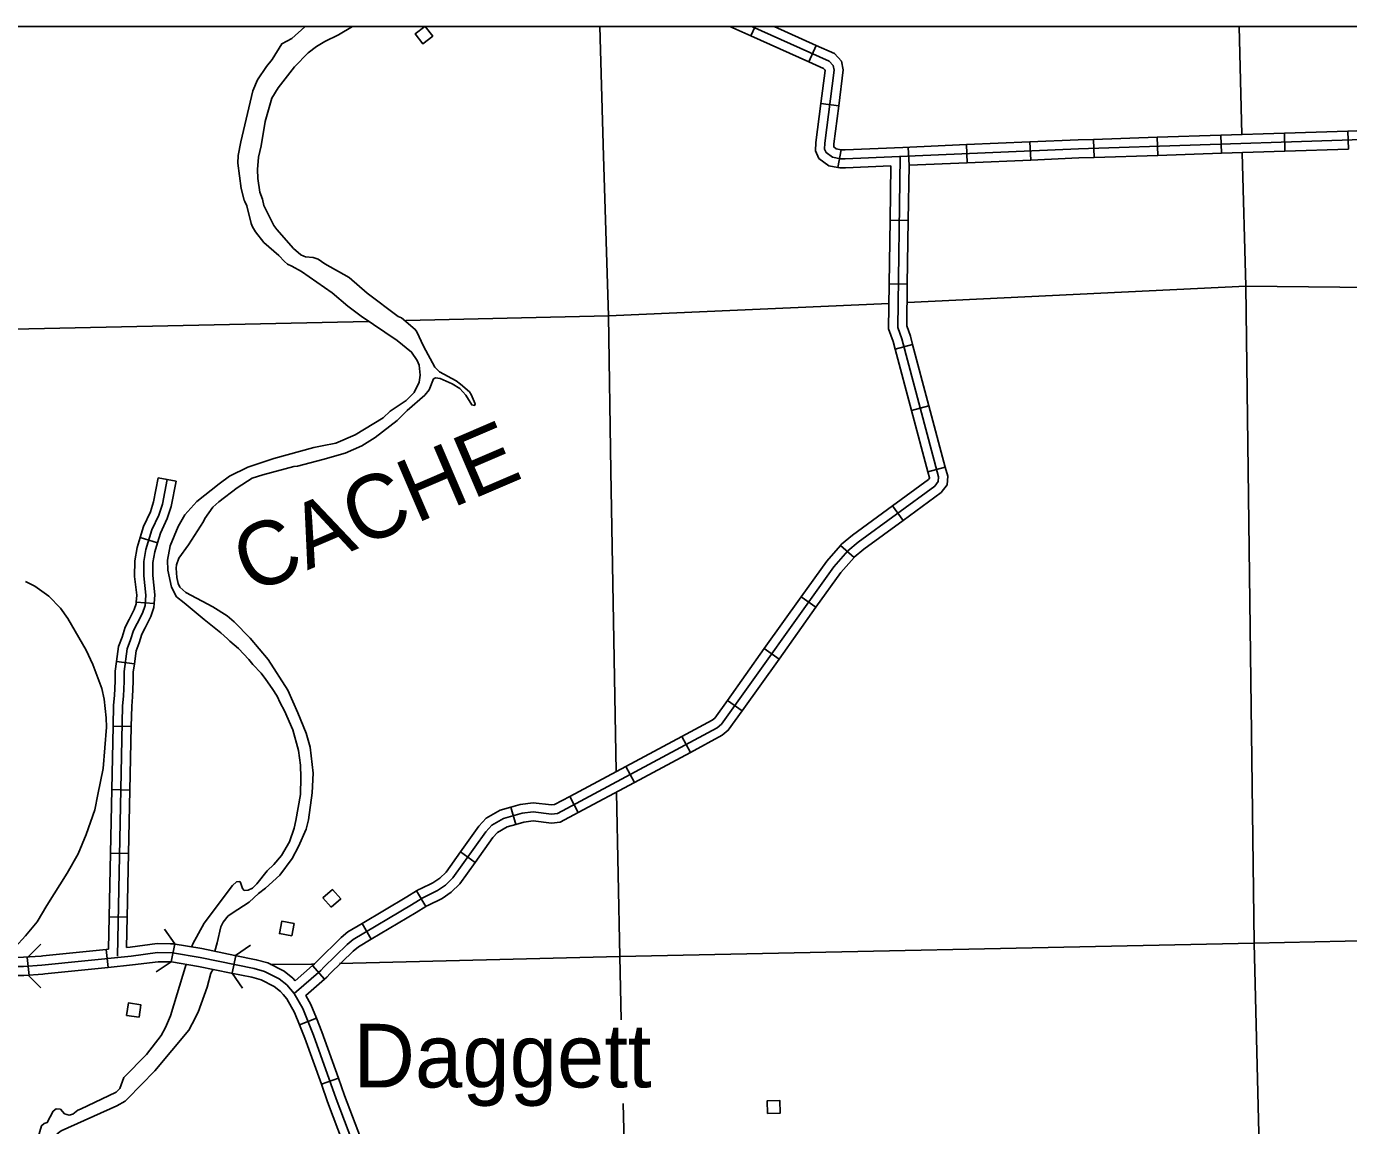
# Model space of a CAD drawing. Extents: x 1084508 to 1142749, y 1057638 to 1093403.
# Drawn here: x 1089174 to 1092618, y 1090540 to 1093403 of the extents above; entities that cross this region are included whole.
import ezdxf

# ---------------------------------------------------------------- set-up
doc = ezdxf.new("R2010")
doc.units = 0
for name, color, linetype in [('DSN_DRFT_Named-Boundary', 7, 'Continuous'), ('Level 24', 7, 'Continuous'), ('Level 32', 7, 'Continuous'), ('Level 35', 7, 'Continuous'), ('Level 38', 7, 'Continuous'), ('Level 5', 7, 'Continuous'), ('Level 56', 7, 'Continuous'), ('Level 9', 7, 'Continuous')]:
    doc.layers.add(name, color=color, linetype=linetype)

msp = doc.modelspace()

# ---------------------------------------------------------------- linework, layer by layer
at = {"layer": 'DSN_DRFT_Named-Boundary'}
msp.add_lwpolyline([(1084507.9, 1057640), (1142749.2, 1057640), (1142749.2, 1093403.4), (1084507.9, 1093403.4)], close=True, dxfattribs=at)
at = {"layer": 'Level 32'}
for p, q in [((1091006.5, 1093403.4), (1091061.2, 1093378.8)), ((1091061.2, 1093378.8), (1091072.2, 1093403.4)), ((1091121.4, 1093403.4), (1091231.6, 1093353.9)), ((1091212.3, 1093310.9), (1091231.6, 1093353.9)), ((1091243.2, 1093202.5), (1091289.9, 1093196.5)), ((1092617.9, 1093083.7), (1092616.3, 1093130.8)), ((1091624.4, 1093048.4), (1091622.4, 1093095.4)), ((1091790, 1093055.4), (1091788, 1093102.4)), ((1091955.3, 1093062), (1091953.8, 1093109.1)), ((1092121, 1093067.4), (1092119.4, 1093114.5)), ((1092286.6, 1093072.9), (1092285.1, 1093119.9)), ((1092452.2, 1093078.3), (1092450.7, 1093125.4)), ((1091287.9, 1093036.1), (1091296.6, 1093082.3)), ((1091473.1, 1093041.5), (1091471.1, 1093088.6)), ((1091423.9, 1092898.3), (1091471, 1092897.6)), ((1091421.6, 1092732.6), (1091468.6, 1092731.9)), ((1091436.8, 1092563), (1091482.3, 1092575.1)), ((1091479.4, 1092402.9), (1091524.9, 1092415)), ((1091522.1, 1092242.7), (1091567.6, 1092254.8)), ((1089517.7, 1092227.7), (1089563.9, 1092218.6)), ((1091430.1, 1092154.5), (1091457.9, 1092116.6)), ((1089470.4, 1092072.2), (1089515.4, 1092058.4)), ((1091294.5, 1092050.9), (1091329.8, 1092019.7)), ((1089460.2, 1091903.4), (1089507.1, 1091899.7)), ((1091192.4, 1091917.5), (1091230.7, 1091890.2)), ((1091096.1, 1091782.6), (1091134.4, 1091755.3)), ((1089408.7, 1091748.7), (1089455.4, 1091742.5)), ((1090999.8, 1091647.7), (1091038.2, 1091620.4)), ((1089400.1, 1091580.8), (1089447.2, 1091579.8)), ((1090881.5, 1091553.6), (1090903.7, 1091512.1)), ((1090735.4, 1091475.4), (1090757.6, 1091433.9)), ((1089396.6, 1091415.1), (1089443.7, 1091414.1)), ((1090589.2, 1091397.2), (1090611.5, 1091355.7)), ((1090435.5, 1091369.6), (1090448.6, 1091324.4)), ((1089393.2, 1091249.4), (1089440.3, 1091248.4)), ((1090304.4, 1091252.8), (1090342.7, 1091225.5)), ((1090190.2, 1091151.3), (1090214.8, 1091111.1)), ((1089389.7, 1091083.7), (1089436.8, 1091082.7)), ((1090048.3, 1091066.3), (1090072.4, 1091025.8)), ((1089386.7, 1090951.8), (1089382, 1090998.7)), ((1089551.5, 1090966.7), (1089560.4, 1091013)), ((1089181.2, 1090931), (1089176.4, 1090977.8)), ((1089709.9, 1090936.8), (1089719.3, 1090982.9)), ((1089919.5, 1090956.8), (1089950.4, 1090921.3)), ((1089885.8, 1090802.3), (1089929.5, 1090819.8)), ((1089942.3, 1090647.5), (1089986.7, 1090663.3))]:
    msp.add_line(p, q, dxfattribs=at)
for points in [[(1091061.2, 1093378.8), (1091212.3, 1093310.9)], [(1091064, 1093403.4), (1091264.8, 1093313.2), (1091275.5, 1093301.4), (1091278, 1093289.3), (1091253.8, 1093099.2), (1091253.1, 1093084), (1091257.2, 1093074.7), (1091273.4, 1093062.8), (1091294.9, 1093058.7)], [(1091231.6, 1093353.9), (1091278.9, 1093332.6), (1091297.3, 1093312.5), (1091301.9, 1093290.2), (1091289.9, 1093196.5)], [(1091212.3, 1093310.9), (1091250.7, 1093293.7), (1091253.8, 1093290.3), (1091254.2, 1093288.4), (1091243.2, 1093202.5)], [(1091243.2, 1093202.5), (1091230.3, 1093101.2), (1091229.4, 1093079.6), (1091238.2, 1093059.5), (1091263.8, 1093040.6), (1091287.9, 1093036.1)], [(1091289.9, 1093196.5), (1091277.3, 1093097.2), (1091276.9, 1093089.5), (1091283.1, 1093084.9), (1091296.6, 1093082.3)], [(1091294.9, 1093058.7), (1091307.1, 1093058.4), (1091914.4, 1093084.2), (1092865.4, 1093115.4), (1093339.9, 1093125.6), (1093745.9, 1093130.1), (1093949.8, 1093129.8)], [(1092450.7, 1093125.4), (1092616.3, 1093130.8)], [(1092616.3, 1093130.8), (1092782, 1093136.2)], [(1091456.8, 1093088.4), (1091622.4, 1093095.4)], [(1091622.4, 1093095.4), (1091788, 1093102.4)], [(1091788, 1093102.4), (1091913.5, 1093107.8), (1091953.8, 1093109.1)], [(1091953.8, 1093109.1), (1092119.4, 1093114.5)], [(1092119.4, 1093114.5), (1092285.1, 1093119.9)], [(1092285.1, 1093119.9), (1092450.7, 1093125.4)], [(1091449.7, 1093063.7), (1091443.5, 1092619.3), (1091454.1, 1092589.5), (1091549.9, 1092229.6), (1091549.1, 1092217.6), (1091540, 1092205.9), (1091340.7, 1092059.9), (1091314, 1092037.4), (1091277.1, 1091995.7), (1090984.5, 1091585.7), (1090973.4, 1091576.1), (1090557.2, 1091353.3)], [(1091296.6, 1093082.3), (1091297.4, 1093082.2), (1091306.8, 1093082), (1091456.8, 1093088.4)], [(1091790, 1093055.4), (1091915.3, 1093060.7), (1091955.3, 1093062)], [(1091955.3, 1093062), (1092121, 1093067.4)], [(1092121, 1093067.4), (1092286.6, 1093072.9)], [(1092286.6, 1093072.9), (1092452.2, 1093078.3)], [(1092452.2, 1093078.3), (1092617.9, 1093083.7)], [(1091287.9, 1093036.1), (1091292.5, 1093035.2), (1091307.3, 1093034.9), (1091425.9, 1093039.9)], [(1091425.9, 1093039.9), (1091423.9, 1092898.3)], [(1091473, 1093041.9), (1091471, 1092897.6)], [(1091473, 1093041.9), (1091624.4, 1093048.4)], [(1091624.4, 1093048.4), (1091790, 1093055.4)], [(1091423.9, 1092898.3), (1091421.6, 1092732.6)], [(1091471, 1092897.6), (1091468.6, 1092731.9)], [(1091421.6, 1092732.6), (1091419.9, 1092615.4), (1091431.6, 1092582.5), (1091436.8, 1092563)], [(1091468.6, 1092731.9), (1091467.1, 1092623.2), (1091476.6, 1092596.4), (1091482.3, 1092575.1)], [(1091436.8, 1092563), (1091479.4, 1092402.9)], [(1091482.3, 1092575.1), (1091524.9, 1092415)], [(1091524.9, 1092415), (1091567.6, 1092254.8)], [(1091479.4, 1092402.9), (1091522.1, 1092242.7)], [(1091522.1, 1092242.7), (1091526.2, 1092227.3), (1091526.1, 1092226.4), (1091523.5, 1092223), (1091430.1, 1092154.5)], [(1091567.6, 1092254.8), (1091573.7, 1092231.9), (1091572.1, 1092208.8), (1091556.6, 1092188.9), (1091457.9, 1092116.6)], [(1089540.8, 1092223.1), (1089528.2, 1092158.7), (1089519.1, 1092130.3), (1089501, 1092091.9), (1089485.3, 1092040.3), (1089479.9, 1092009.1), (1089479.6, 1091972), (1089485.2, 1091921.8), (1089483.1, 1091894.6), (1089476.3, 1091874.9), (1089462.7, 1091847.5), (1089453.1, 1091829.7), (1089445.5, 1091805), (1089436.9, 1091782), (1089429, 1091722.5), (1089429.1, 1091697.2), (1089427, 1091658.8), (1089424.8, 1091633.5), (1089411.1, 1090981.6)], [(1089517.7, 1092227.7), (1089505.4, 1092164.6), (1089497.1, 1092139), (1089479, 1092100.4), (1089470.4, 1092072.2)], [(1089563.9, 1092218.6), (1089551, 1092152.9), (1089541, 1092121.7), (1089523, 1092083.4), (1089515.4, 1092058.4)], [(1091430.1, 1092154.5), (1091326.2, 1092078.4), (1091297.5, 1092054.3), (1091294.5, 1092050.9)], [(1091457.9, 1092116.6), (1091355.2, 1092041.3), (1091330.4, 1092020.5), (1091329.8, 1092019.7)], [(1089470.4, 1092072.2), (1089462.3, 1092045.7), (1089456.3, 1092011.3), (1089456, 1091970.8), (1089461.6, 1091921.4), (1089460.2, 1091903.4)], [(1089515.4, 1092058.4), (1089508.2, 1092034.8), (1089503.4, 1092007), (1089503.2, 1091973.2), (1089508.9, 1091922.2), (1089507.1, 1091899.7)], [(1091294.5, 1092050.9), (1091258.6, 1092010.4), (1091192.4, 1091917.5)], [(1091329.8, 1092019.7), (1091295.5, 1091981), (1091230.7, 1091890.2)], [(1089460.2, 1091903.4), (1089459.9, 1091899.5), (1089454.5, 1091884), (1089441.8, 1091858.3), (1089431.3, 1091838.8), (1089423.2, 1091812.6), (1089413.9, 1091787.8), (1089408.7, 1091748.7)], [(1089507.1, 1091899.7), (1089506.3, 1091889.8), (1089498, 1091865.8), (1089483.6, 1091836.6), (1089474.9, 1091820.5), (1089467.8, 1091797.4), (1089459.9, 1091776.3), (1089455.4, 1091742.5)], [(1091192.4, 1091917.5), (1091096.1, 1091782.6)], [(1091230.7, 1091890.2), (1091134.4, 1091755.3)], [(1091096.1, 1091782.6), (1090999.8, 1091647.7)], [(1091134.4, 1091755.3), (1091038.2, 1091620.4)], [(1089408.7, 1091748.7), (1089405.5, 1091724.1), (1089405.5, 1091697.9), (1089403.5, 1091660.5), (1089401.2, 1091634.8), (1089400.1, 1091580.8)], [(1089455.4, 1091742.5), (1089452.6, 1091721), (1089452.6, 1091696.6), (1089450.5, 1091657.2), (1089448.3, 1091632.3), (1089447.2, 1091579.8)], [(1090999.8, 1091647.7), (1090967, 1091601.7), (1090960, 1091595.7), (1090881.5, 1091553.6)], [(1091038.2, 1091620.4), (1091002, 1091569.8), (1090986.7, 1091556.6), (1090903.7, 1091512.1)], [(1089400.1, 1091580.8), (1089396.6, 1091415.1)], [(1089447.2, 1091579.8), (1089443.7, 1091414.1)], [(1090881.5, 1091553.6), (1090735.4, 1091475.4)], [(1090903.7, 1091512.1), (1090757.6, 1091433.9)], [(1090735.4, 1091475.4), (1090589.2, 1091397.2)], [(1089396.6, 1091415.1), (1089393.2, 1091249.4)], [(1089443.7, 1091414.1), (1089440.3, 1091248.4)], [(1090757.6, 1091433.9), (1090611.5, 1091355.7)], [(1090589.2, 1091397.2), (1090549.9, 1091376.1), (1090542.1, 1091375.2), (1090494, 1091380.9), (1090460.4, 1091376.8), (1090435.5, 1091369.6)], [(1090557.2, 1091353.3), (1090542.1, 1091351.5), (1090494, 1091357.2), (1090465.2, 1091353.7), (1090417.2, 1091339.9), (1090386.4, 1091322.3), (1090370.6, 1091305.4), (1090285, 1091185), (1090265.6, 1091166.6), (1090244.7, 1091152), (1090210.1, 1091134.9), (1090206.3, 1091133.5)], [(1090435.5, 1091369.6), (1090408, 1091361.7), (1090371.6, 1091341), (1090352.3, 1091320.3), (1090304.4, 1091252.8)], [(1090611.5, 1091355.7), (1090564.4, 1091330.5), (1090542.1, 1091327.8), (1090494.1, 1091333.5), (1090469.9, 1091330.6), (1090448.6, 1091324.4)], [(1090448.6, 1091324.4), (1090426.4, 1091318), (1090401.2, 1091303.7), (1090388.9, 1091290.5), (1090342.7, 1091225.5)], [(1089393.2, 1091249.4), (1089389.7, 1091083.7)], [(1089440.3, 1091248.4), (1089436.8, 1091082.7)], [(1090304.4, 1091252.8), (1090267.2, 1091200.5), (1090250.7, 1091184.9), (1090232.7, 1091172.3), (1090200.7, 1091156.6), (1090196, 1091154.8), (1090190.2, 1091151.3)], [(1090342.7, 1091225.5), (1090302.9, 1091169.5), (1090280.5, 1091148.3), (1090256.7, 1091131.7), (1090219.4, 1091113.3), (1090216.7, 1091112.3), (1090214.8, 1091111.1)], [(1090206.3, 1091133.5), (1090176.8, 1091115.4), (1090025.1, 1091025.1), (1090009.3, 1091012.1), (1089948.8, 1090952.6), (1089940.7, 1090944), (1089871.4, 1090883.8), (1089894, 1090845.3), (1089921.7, 1090775.8), (1089980.8, 1090609.8), (1090033.8, 1090470), (1090050, 1090423.4), (1090089.8, 1090319.7), (1090098.5, 1090282), (1090100.7, 1090263.4), (1090110.6, 1090064), (1090110.3, 1090055.8)], [(1090190.2, 1091151.3), (1090164.6, 1091135.6), (1090048.3, 1091066.3)], [(1090214.8, 1091111.1), (1090189, 1091095.3), (1090072.4, 1091025.8)], [(1089389.7, 1091083.7), (1089388, 1090999.3)], [(1089436.8, 1091082.7), (1089435.2, 1091004.1)], [(1090048.3, 1091066.3), (1090011.6, 1091044.4), (1089993.6, 1091029.7), (1089932, 1090969.1), (1089924.4, 1090961.1), (1089919.5, 1090956.8)], [(1089217.1, 1090981.9), (1089382, 1090998.7)], [(1089382, 1090998.7), (1089388, 1090999.3)], [(1089435.2, 1091004.1), (1089444.7, 1091005), (1089514.4, 1091014.1), (1089549.4, 1091013.7)], [(1089549.4, 1091013.7), (1089556.3, 1091013.6), (1089630.9, 1091001), (1089716.8, 1090983.4)], [(1090072.4, 1091025.8), (1090038.7, 1091005.8), (1090025.1, 1090994.6), (1089965.6, 1090936.1), (1089957, 1090927), (1089950.4, 1090921.3)], [(1089054, 1090978.2), (1089097, 1090978), (1089166.1, 1090978.3), (1089212.5, 1090981.5), (1089217.1, 1090981.9)], [(1089097, 1090954.4), (1089166.9, 1090954.8), (1089214.5, 1090958), (1089447.4, 1090981.6), (1089515.7, 1090990.5), (1089554.2, 1090990.1), (1089626.6, 1090977.8)], [(1089386.7, 1090951.8), (1089450.1, 1090958.3), (1089517.1, 1090966.9), (1089548.9, 1090966.6)], [(1089548.9, 1090966.6), (1089552.1, 1090966.5), (1089622.3, 1090954.7), (1089707.4, 1090937.3)], [(1089626.6, 1090977.8), (1089767.2, 1090949.1), (1089794, 1090941.7), (1089832.5, 1090921.9), (1089852, 1090906.7), (1089871.4, 1090883.8)], [(1089716.8, 1090983.4), (1089772.7, 1090972), (1089802.6, 1090963.7), (1089845.2, 1090941.8), (1089868.4, 1090923.8), (1089873.9, 1090917.2)], [(1089053.7, 1090931.2), (1089097, 1090930.9), (1089167.8, 1090931.2), (1089216.5, 1090934.5), (1089221.8, 1090935.1)], [(1089221.8, 1090935.1), (1089386.7, 1090951.8)], [(1089707.4, 1090937.3), (1089761.7, 1090926.2), (1089785.4, 1090919.7), (1089819.7, 1090902), (1089835.6, 1090889.6), (1089842.8, 1090881.1)], [(1089919.5, 1090956.8), (1089873.9, 1090917.2)], [(1089950.4, 1090921.3), (1089901.6, 1090878.8), (1089915.2, 1090855.7), (1089929.5, 1090819.8)], [(1089842.8, 1090881.1), (1089852.1, 1090870.1)], [(1089852.1, 1090870.1), (1089872.7, 1090834.9), (1089885.8, 1090802.3)], [(1089885.8, 1090802.3), (1089899.7, 1090767.4), (1089942.3, 1090647.5)], [(1089929.5, 1090819.8), (1089943.7, 1090784.1), (1089986.7, 1090663.3)], [(1089986.7, 1090663.3), (1090002.9, 1090617.9), (1090044.4, 1090508.5)], [(1089942.3, 1090647.5), (1089958.7, 1090601.6), (1090000.4, 1090491.8)]]:
    msp.add_lwpolyline(points, dxfattribs=at)
at = {"layer": 'Level 35'}
msp.add_lwpolyline([(1089115, 1090977.8), (1089144.9, 1091005), (1089171.5, 1091034.3), (1089202.3, 1091070.7), (1089226.9, 1091113.2), (1089280.7, 1091197.2), (1089308.8, 1091247.7), (1089329.6, 1091298.5), (1089352.3, 1091362.8), (1089360, 1091402.7), (1089373.9, 1091470), (1089383.1, 1091578), (1089382.2, 1091602.6), (1089376.3, 1091651.2), (1089370.6, 1091678.4), (1089347.2, 1091741.4), (1089329.7, 1091778.2), (1089282, 1091861.2), (1089263.3, 1091888.2), (1089232.2, 1091919.5), (1089196.4, 1091944.9), (1089172, 1091957.2)], dxfattribs=at)
at = {"layer": 'Level 38'}
for points in [[(1089534, 1091052), (1089560.4, 1091013)], [(1089178.7, 1090979.3), (1089212, 1091012.6)], [(1089719.1, 1090983.3), (1089758.1, 1091009.6)], [(1089551.5, 1090966.7), (1089512.5, 1090940.4)], [(1089212, 1090898.9), (1089178.7, 1090932.2)], [(1089736.6, 1090898), (1089710.2, 1090937)]]:
    msp.add_lwpolyline(points, dxfattribs=at)
at = {"layer": 'Level 5'}
msp.add_line((1092333.1, 1093403.4), (1092339.6, 1093122), dxfattribs=at)
for points in [[(1090667.4, 1093403.4), (1090677, 1093065), (1090689.9, 1092649.1), (1090696.7, 1092244.9), (1090710.5, 1091462.7)], [(1092340.9, 1093073.7), (1092350.2, 1092727), (1092372.1, 1091014.9)], [(1091469.1, 1092684.2), (1092350.2, 1092727), (1093903.8, 1092710.2), (1094002.1, 1092708.2), (1094048.6, 1092708.7)], [(1090162.3, 1092637.3), (1090689.9, 1092649.1), (1091421.6, 1092681.9)], [(1087338.7, 1092632.1), (1089018.6, 1092611.7), (1090064.8, 1092635.1)], [(1090711.5, 1091407.7), (1090719.6, 1090980.1), (1090723.5, 1090815.2)], [(1092767.4, 1091023.5), (1092372.1, 1091014.9), (1090719.6, 1090980.1), (1089989.6, 1090961.9)], [(1092372.1, 1091014.9), (1092392.3, 1090201.3)], [(1089923, 1090960.8), (1089916.7, 1090960.8), (1089810.1, 1090959.9)], [(1090728.6, 1090597.6), (1090734.2, 1090360.7)]]:
    msp.add_lwpolyline(points, dxfattribs=at)
at = {"layer": 'Level 56'}
msp.add_lwpolyline([(1090212.5, 1093403.4), (1090232.3, 1093378.1), (1090206.7, 1093357.9), (1090186.4, 1093383.7), (1090211.5, 1093403.4)], dxfattribs=at)
for points in [[(1089968.3, 1091108.7), (1089946.6, 1091133.1), (1089971.1, 1091154.8), (1089992.8, 1091130.4)], [(1089865.4, 1091034.1), (1089833.3, 1091040.2), (1089839.4, 1091072.4), (1089871.5, 1091066.3)], [(1089435.1, 1090827.1), (1089439.6, 1090859.4), (1089472.1, 1090854.9), (1089467.6, 1090822.5)], [(1091104.8, 1090571.5), (1091103.5, 1090604.1), (1091136.3, 1090605.4), (1091137.5, 1090572.7)]]:
    msp.add_lwpolyline(points, close=True, dxfattribs=at)
at = {"layer": 'Level 9'}
for points in [[(1089902.7, 1093403.4), (1089899.3, 1093401.9), (1089865.6, 1093371.6), (1089839.8, 1093358.4), (1089814.3, 1093317.1), (1089799.9, 1093298.6), (1089776.4, 1093264.2), (1089763.8, 1093235.9), (1089732.5, 1093102.7), (1089725.3, 1093066.9), (1089725.1, 1093047.3), (1089733.9, 1092981.2), (1089741.3, 1092951), (1089742.7, 1092947.5)], [(1090023.1, 1093403.4), (1089987, 1093381.2), (1089951.7, 1093364.2), (1089929.9, 1093351.1), (1089908.4, 1093334.2), (1089872, 1093298.2), (1089830, 1093243.1), (1089813, 1093216.6), (1089795.7, 1093156.1), (1089785.8, 1093092.7), (1089778.7, 1093062.6), (1089776.1, 1093030.3), (1089777.3, 1093007.4), (1089782.1, 1092971.3), (1089788.7, 1092953.6), (1089792.5, 1092937.1), (1089819, 1092884.8), (1089826, 1092874.7), (1089869.4, 1092825), (1089888.6, 1092808.7), (1089896.3, 1092804.9)], [(1089742.7, 1092947.5), (1089748.5, 1092935.7), (1089759.6, 1092889.9), (1089763.1, 1092880.9), (1089770.5, 1092868.5), (1089792.9, 1092840.4), (1089831.2, 1092806.4), (1089846.4, 1092790.7), (1089854.2, 1092784.1), (1089865.1, 1092778.8), (1089890.8, 1092764.7), (1089970.6, 1092709.7), (1090011, 1092674.4), (1090046.3, 1092648.9), (1090139.9, 1092585.6), (1090177.3, 1092554.9), (1090192.3, 1092532.8), (1090197.4, 1092521), (1090199.3, 1092495.3), (1090197.2, 1092476.9), (1090183.7, 1092449.9), (1090163.4, 1092429), (1090121.6, 1092400.7), (1090103.3, 1092383.3), (1090030.6, 1092339.6), (1089980.1, 1092317.3), (1089944.8, 1092311.2), (1089922.9, 1092306.3)], [(1089896.3, 1092804.9), (1089901.4, 1092802.9), (1089921.3, 1092801.4), (1089933.7, 1092797.5), (1089951.8, 1092785.2), (1090014.5, 1092749.2), (1090061.7, 1092708.7), (1090142, 1092648.1), (1090151, 1092644), (1090187, 1092613.9), (1090191.4, 1092607.4), (1090208.5, 1092570.6), (1090237.6, 1092515.3), (1090250.3, 1092503.8), (1090293.1, 1092480.5), (1090305.1, 1092471.5), (1090327.8, 1092451.3), (1090332.5, 1092444.8), (1090342.9, 1092420), (1090341.4, 1092416.2), (1090334.1, 1092417.2), (1090319, 1092443), (1090303.3, 1092459.8), (1090282.7, 1092472.6)], [(1090282.7, 1092472.6), (1090251.9, 1092485.9), (1090239.4, 1092487.5), (1090234.6, 1092485.2), (1090223.4, 1092457.1), (1090212, 1092442.8), (1090166.2, 1092402.4), (1090140.1, 1092376.5), (1090082.6, 1092332.1), (1090047.4, 1092311), (1090004.1, 1092292), (1089946.1, 1092275.4), (1089880.3, 1092258.1), (1089870.6, 1092257.1), (1089789.5, 1092235.2), (1089762.5, 1092226.3), (1089723.4, 1092201.5), (1089675.6, 1092164.8), (1089660.1, 1092151), (1089638.8, 1092121.5), (1089635.3, 1092113.8), (1089596, 1092052.8), (1089571.5, 1092018.5), (1089565.2, 1092000.6)], [(1089922.9, 1092306.3), (1089818.2, 1092278.1), (1089751, 1092255.5), (1089702.7, 1092231.9), (1089676.4, 1092211.7), (1089618.3, 1092166.1), (1089586.8, 1092130.6), (1089569.7, 1092100.6), (1089548.6, 1092050.1), (1089541.5, 1092012.6), (1089542.4, 1091986.9), (1089551.6, 1091942.2), (1089565.1, 1091917.8), (1089585.2, 1091902.2), (1089637.3, 1091858.1), (1089680.1, 1091823.8), (1089698.3, 1091808.4), (1089703.6, 1091802), (1089726.3, 1091782.7), (1089753.2, 1091754.1), (1089763.8, 1091741.1), (1089785.4, 1091718.8), (1089797.3, 1091702.2), (1089813.9, 1091678.9)], [(1089565.2, 1092000.6), (1089564.3, 1091992.4), (1089565.8, 1091967.6), (1089569.2, 1091952), (1089573.7, 1091942.7), (1089589.6, 1091929.1), (1089659.3, 1091891.7), (1089697.4, 1091867.6), (1089715.3, 1091851.9), (1089756.5, 1091810), (1089803.6, 1091754.4), (1089854.7, 1091674.4), (1089881.5, 1091615.3), (1089902.6, 1091562.5), (1089913.1, 1091525.7), (1089921.3, 1091458), (1089918.2, 1091406.5), (1089908.5, 1091336.3), (1089902.5, 1091312.1), (1089882.4, 1091266.6), (1089866.3, 1091235.5), (1089834.5, 1091192.4), (1089797, 1091158.5), (1089778.3, 1091144.3), (1089754.6, 1091122.3), (1089724.4, 1091102.9), (1089699.9, 1091086.2)], [(1089813.9, 1091678.9), (1089827, 1091658.9), (1089835.2, 1091641.3), (1089846.3, 1091620.6), (1089868.3, 1091571.3), (1089882.9, 1091517), (1089888.1, 1091478.5), (1089888.7, 1091446.7), (1089888.4, 1091402.6), (1089875.8, 1091335), (1089871.2, 1091315), (1089859, 1091279.3), (1089838.9, 1091243.9), (1089819, 1091219.8), (1089801.6, 1091203.4), (1089774.6, 1091169.7), (1089763, 1091158.5), (1089751.6, 1091153), (1089741.5, 1091152.7), (1089736.9, 1091157.9), (1089731.9, 1091172.8), (1089729.6, 1091175.5), (1089721.2, 1091174.6), (1089710.8, 1091165.4), (1089637, 1091067.5), (1089607.5, 1091013.8), (1089604.9, 1091006.8)], [(1089699.9, 1091086.2), (1089686.6, 1091069.6), (1089680.8, 1091057.5), (1089671, 1091015.8), (1089664.5, 1090994)], [(1089590.2, 1090960.6), (1089549.6, 1090826.1), (1089536.8, 1090795.5), (1089524.7, 1090774.3), (1089486.8, 1090725.5), (1089427.7, 1090665.6), (1089417.4, 1090636.6), (1089407.7, 1090626.7), (1089315.2, 1090582.3), (1089308, 1090580.2), (1089295.2, 1090569.9), (1089285.2, 1090567.4), (1089273.7, 1090570.7), (1089262.6, 1090582.3), (1089251.5, 1090584), (1089243.9, 1090577.1), (1089228.6, 1090547.6), (1089220.2, 1090545.4), (1089213.2, 1090539.5), (1089191.4, 1090465.2), (1089190.2, 1090446.6), (1089190.8, 1090433.1)], [(1089660.4, 1090947), (1089654.4, 1090937.4), (1089644.7, 1090900.2), (1089621.6, 1090835.7), (1089605.8, 1090804.6), (1089596.9, 1090788.2), (1089508.6, 1090682.8), (1089437.3, 1090609.3), (1089431.2, 1090603.7), (1089409.3, 1090591.5), (1089265, 1090526), (1089254, 1090518.3), (1089240.9, 1090504), (1089232.4, 1090488.2), (1089230.3, 1090451.9), (1089232.9, 1090431.5)]]:
    msp.add_lwpolyline(points, dxfattribs=at)

# ---------------------------------------------------------------- texts
at = {"layer": 'Level 24'}
msp.add_text('Daggett', height=165.73, dxfattribs=at).set_placement((1090026.1, 1090639.3))
at = {"layer": 'Level 9'}
msp.add_text('CACHE', height=165.73, rotation=23.2107, dxfattribs=at).set_placement((1089758.7, 1091923.2))

doc.saveas('drawing.dxf')
